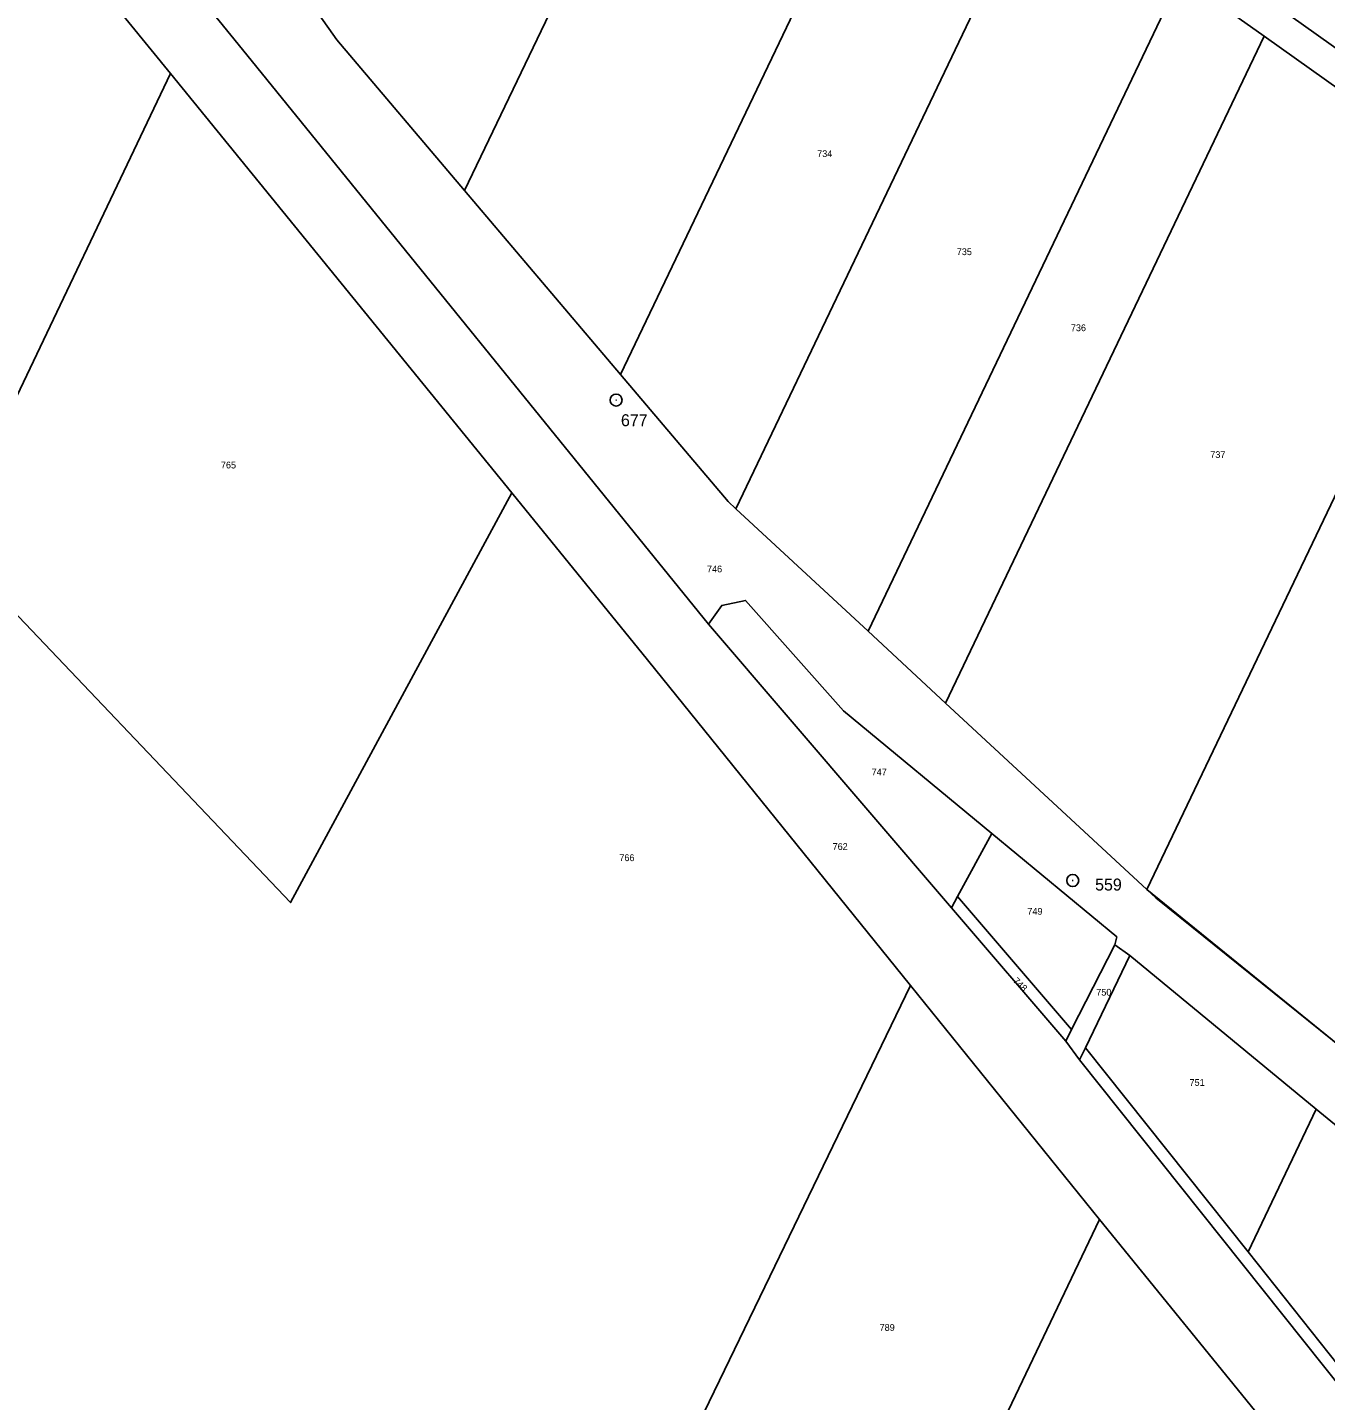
# Model space of a CAD drawing. Extents: x -504997 to -503568, y -1079870 to -1078007.
# Drawn here: x -504219.1 to -503893.5, y -1079531.2 to -1079186.7 of the extents above; entities that cross this region are included whole.
import ezdxf

# ---------------------------------------------------------------- set-up
doc = ezdxf.new("R2010")
doc.units = 0
for name, color, linetype in [('Hranice parcel', 7, 'Continuous'), ('Parcelní čísla', 7, 'Continuous'), ('Vrstva 30', 7, 'Continuous'), ('Vrstva 31', 7, 'Continuous'), ('Vrstva 32', 7, 'Continuous'), ('Vrstva 54', 7, 'Continuous')]:
    doc.layers.add(name, color=color, linetype=linetype)

msp = doc.modelspace()

# ---------------------------------------------------------------- linework, layer by layer
at = {"layer": 'Hranice parcel'}
for p, q in [((-504045.55, -1079093.99), (-504109.47, -1079227.67)), ((-504070.38, -1079273.8), (-503999.6, -1079125.68)), ((-503965.74, -1079149.03), (-504041.43, -1079307.47)), ((-503929.86, -1079174.07), (-504008.27, -1079338.19)), ((-503908.92, -1079188.96), (-503929.86, -1079174.07)), ((-503905.42, -1079181.64), (-503850.5, -1079220.7)), ((-503908.92, -1079188.96), (-503988.82, -1079356.2)), ((-503854.56, -1079227.62), (-503908.92, -1079188.96)), ((-504183.22, -1079198.33), (-504239.26, -1079315.79)), ((-504183.22, -1079198.33), (-504097.67, -1079303.47)), ((-504070.38, -1079273.8), (-504109.47, -1079227.67)), ((-503854.56, -1079227.62), (-503938.33, -1079402.97)), ((-504008.27, -1079338.19), (-504041.43, -1079307.47)), ((-503987.33, -1079407.59), (-504048.32, -1079336.41)), ((-503988.82, -1079356.2), (-504008.27, -1079338.19)), ((-503938.33, -1079402.97), (-503988.82, -1079356.2)), ((-503985.81, -1079404.77), (-503977.25, -1079388.9)), ((-503987.33, -1079407.59), (-503985.81, -1079404.77)), ((-503958.71, -1079441.01), (-503987.33, -1079407.59)), ((-503985.81, -1079404.77), (-503957.24, -1079438.12)), ((-503946.4, -1079416.88), (-503957.24, -1079438.12)), ((-503946.4, -1079416.88), (-503942.64, -1079419.51)), ((-503953.77, -1079442.68), (-503942.64, -1079419.51)), ((-503942.64, -1079419.51), (-503895.86, -1079458.07)), ((-503997.67, -1079427.08), (-503950.22, -1079485.75)), ((-503957.24, -1079438.12), (-503958.71, -1079441.01)), ((-503955.21, -1079445.68), (-503958.71, -1079441.01)), ((-503955.21, -1079445.68), (-503953.77, -1079442.68)), ((-503953.77, -1079442.68), (-503912.97, -1079493.9)), ((-503895.86, -1079458.07), (-503912.97, -1079493.9)), ((-503895.86, -1079458.07), (-503867.31, -1079481.6)), ((-503950.22, -1079485.75), (-503899.25, -1079548.46)), ((-503912.97, -1079493.9), (-503888.1, -1079525.12))]:
    msp.add_line(p, q, dxfattribs=at)
for points in [[(-504048.32, -1079336.41), (-504164.13, -1079193.65), (-504189.98, -1079161.66), (-504303.4, -1079021.3), (-504338.19, -1078978.95)], [(-504221.12, -1079152.74), (-504216.11, -1079157.97), (-504183.22, -1079198.33)], [(-504109.47, -1079227.67), (-504141.49, -1079189.89), (-504150.39, -1079177.22)], [(-504041.43, -1079307.47), (-504043.38, -1079305.66), (-504070.38, -1079273.8)], [(-504097.67, -1079303.47), (-504153.14, -1079406.27), (-504239.26, -1079315.79)], [(-503997.67, -1079427.08), (-504063.57, -1079345.38), (-504097.67, -1079303.47)], [(-504048.32, -1079336.41), (-504044.97, -1079331.7), (-504038.99, -1079330.47), (-504014.44, -1079358.14), (-503977.25, -1079388.9)], [(-503977.25, -1079388.9), (-503945.84, -1079414.89), (-503946.4, -1079416.88)], [(-503888.76, -1079443.21), (-503936.1, -1079405.04), (-503938.33, -1079402.97)], [(-504131.58, -1079709.87), (-504110.18, -1079659.69), (-504032.95, -1079500.02), (-503997.67, -1079427.08)], [(-503697.84, -1079765.64), (-503779.17, -1079666.7), (-503806.76, -1079632.06), (-503843.08, -1079586.46), (-503955.21, -1079445.68)], [(-504133.72, -1079869.85), (-504130.18, -1079862.44), (-504053.56, -1079702.06), (-503975.76, -1079539.21), (-503950.22, -1079485.75)]]:
    msp.add_lwpolyline(points, dxfattribs=at)
at = {"layer": 'Vrstva 30'}
for p, q in [((-504071.58, -1079280.21), (-504071.38, -1079280.21)), ((-503957.05, -1079400.72), (-503956.85, -1079400.72))]:
    msp.add_line(p, q, dxfattribs=at)
for centre in [(-504071.48, -1079280.21), (-503956.95, -1079400.72)]:
    msp.add_circle(centre, 1.51, dxfattribs=at)
at = {"layer": 'Vrstva 31'}
for p, q in [((-504071.48, -1079280.21), (-504071.48, -1079280.21)), ((-503956.95, -1079400.72), (-503956.95, -1079400.72))]:
    msp.add_line(p, q, dxfattribs=at)
at = {"layer": 'Vrstva 54'}
for points in [[(-503895.86, -1079458.07), (-503942.64, -1079419.51), (-503946.4, -1079416.88), (-503945.84, -1079414.89), (-503977.25, -1079388.9), (-504014.44, -1079358.14), (-504038.99, -1079330.47), (-504044.97, -1079331.7), (-504048.32, -1079336.41), (-504164.13, -1079193.65), (-504189.98, -1079161.66), (-504303.4, -1079021.3)], [(-504259.1, -1079048.24), (-504191.97, -1079119.35), (-504187.04, -1079125.02), (-504168.33, -1079151.66), (-504150.39, -1079177.22), (-504141.49, -1079189.89), (-504109.47, -1079227.67), (-504070.38, -1079273.8), (-504043.38, -1079305.66), (-504041.43, -1079307.47), (-504008.27, -1079338.19), (-503988.82, -1079356.2), (-503938.33, -1079402.97), (-503888.76, -1079443.21)]]:
    msp.add_lwpolyline(points, dxfattribs=at)

# ---------------------------------------------------------------- texts
at = {"layer": 'Parcelní čísla'}
for s, p in [('734', (-504021.04, -1079219.25)), ('735', (-503986.03, -1079243.85)), ('736', (-503957.41, -1079262.93)), ('737', (-503922.44, -1079294.74)), ('765', (-504170.6, -1079297.36)), ('746', (-504048.68, -1079323.43)), ('747', (-504007.38, -1079374.37)), ('762', (-504017.17, -1079393.05)), ('762', (-504017.17, -1079393.05)), ('766', (-504070.66, -1079395.86)), ('749', (-503968.32, -1079409.3)), ('750', (-503951.04, -1079429.6)), ('751', (-503927.65, -1079452.24)), ('789', (-504005.38, -1079513.68))]:
    msp.add_text(s, height=1.7, dxfattribs=at).set_placement(p)
msp.add_text('748', height=1.7, rotation=316, dxfattribs=at).set_placement((-503972.06, -1079426.09))
at = {"layer": 'Vrstva 32'}
for s, p in [('677', (-504070.26, -1079286.77)), ('559', (-503951.33, -1079403.24))]:
    msp.add_text(s, height=3, dxfattribs=at).set_placement(p)

doc.saveas('drawing.dxf')
